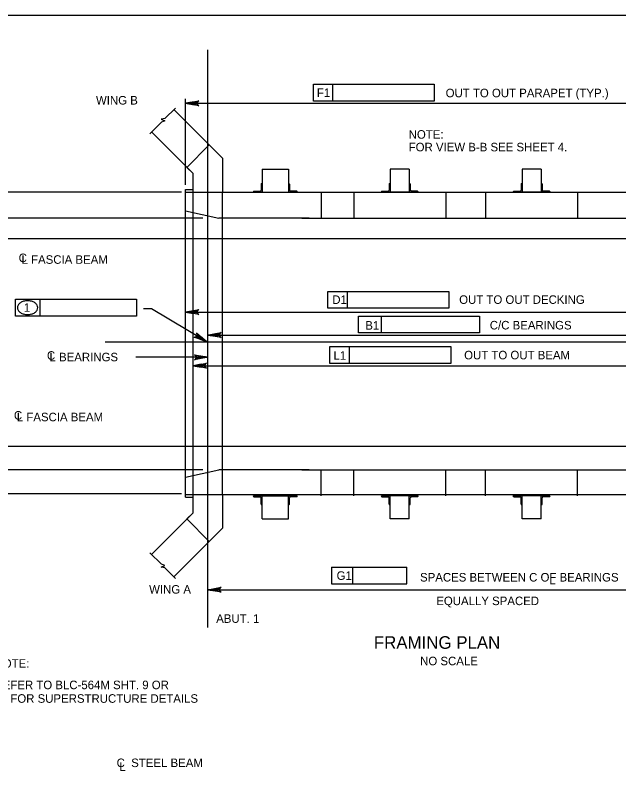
# Model space of a CAD drawing. Extents: x 638175 to 640495, y 294277 to 298435.
# Drawn here: x 638550.4 to 638762.6, y 294590.7 to 294856.5 of the extents above; entities that cross this region are included whole.
import ezdxf

# ---------------------------------------------------------------- set-up
doc = ezdxf.new("R2010")
doc.units = 0
for name, color, linetype in [('2', 7, 'Continuous'), ('3', 7, 'Continuous'), ('4', 7, 'Continuous')]:
    doc.layers.add(name, color=color, linetype=linetype)

msp = doc.modelspace()

# ---------------------------------------------------------------- linework, layer by layer
at = {"layer": '2'}
for p, q in [((638475.46, 294856.46), (639261.46, 294856.46)), ((638623.24, 294806.15), (638606.16, 294823.24)), ((638612.95, 294800.71), (638598.29, 294815.37)), ((638610.74, 294802.91), (638618.61, 294810.78)), ((638623.24, 294806.15), (638623.24, 294794.15)), ((638612.95, 294800.71), (638610.74, 294802.91)), ((638637.18, 294802.24), (638646.41, 294802.24)), ((638637.18, 294802.24), (638637.18, 294794.15)), ((638646.41, 294802.24), (638646.41, 294794.15)), ((638688.9, 294802.24), (638682.17, 294802.24)), ((638682.17, 294802.24), (638682.17, 294794.15)), ((638688.9, 294802.24), (638688.9, 294794.15)), ((638735.26, 294802.24), (638728.53, 294802.24)), ((638735.26, 294802.24), (638728.53, 294802.24)), ((638728.53, 294802.24), (638728.53, 294794.15)), ((638735.26, 294802.24), (638735.26, 294794.15)), ((638612.95, 294794.15), (638612.95, 294800.71)), ((638636.81, 294797.05), (638636.81, 294794.87)), ((638636.99, 294797.24), (638637.18, 294797.24)), ((638637.18, 294797.24), (638637.18, 294794.15)), ((638646.59, 294797.24), (638646.41, 294797.24)), ((638646.41, 294797.24), (638646.41, 294794.15)), ((638646.78, 294797.05), (638646.78, 294794.87)), ((638681.81, 294797.05), (638681.81, 294794.87)), ((638681.99, 294797.24), (638682.17, 294797.24)), ((638682.17, 294797.24), (638682.17, 294794.15)), ((638689.08, 294797.24), (638688.9, 294797.24)), ((638688.9, 294797.24), (638688.9, 294794.15)), ((638689.26, 294797.05), (638689.26, 294794.87)), ((638728.17, 294797.05), (638728.17, 294794.87)), ((638728.35, 294797.24), (638728.53, 294797.24)), ((638728.53, 294797.24), (638728.53, 294794.15)), ((638735.44, 294797.24), (638735.26, 294797.24)), ((638735.26, 294797.24), (638735.26, 294794.15)), ((638735.62, 294797.05), (638735.62, 294794.87)), ((638610.28, 294686.89), (638610.28, 294795.1)), ((638610.28, 294795.1), (638612.95, 294795.1)), ((638610.28, 294794.15), (638813.34, 294794.15)), ((638612.95, 294687.85), (638612.95, 294794.15)), ((638623.24, 294687.85), (638623.24, 294794.15)), ((638634.09, 294794.33), (638634.09, 294794.15)), ((638637.18, 294794.15), (638634.09, 294794.15)), ((638634.27, 294794.51), (638636.45, 294794.51)), ((638637.18, 294794.15), (638646.41, 294794.15)), ((638646.41, 294794.15), (638649.5, 294794.15)), ((638649.32, 294794.51), (638647.14, 294794.51)), ((638649.5, 294794.33), (638649.5, 294794.15)), ((638657.96, 294794.15), (638657.96, 294785.02)), ((638669.36, 294794.15), (638669.36, 294785.02)), ((638679.08, 294794.33), (638679.08, 294794.15)), ((638682.17, 294794.15), (638679.08, 294794.15)), ((638679.26, 294794.51), (638681.44, 294794.51)), ((638688.9, 294794.15), (638682.17, 294794.15)), ((638688.9, 294794.15), (638691.99, 294794.15)), ((638691.81, 294794.51), (638689.63, 294794.51)), ((638691.99, 294794.33), (638691.99, 294794.15)), ((638701.7, 294794.15), (638701.7, 294785.02)), ((638715.73, 294794.15), (638715.73, 294785.02)), ((638725.44, 294794.33), (638725.44, 294794.15)), ((638728.53, 294794.15), (638725.44, 294794.15)), ((638725.63, 294794.51), (638727.81, 294794.51)), ((638736.52, 294794.15), (638727.28, 294794.15)), ((638735.26, 294794.15), (638728.53, 294794.15)), ((638735.26, 294794.15), (638738.35, 294794.15)), ((638738.17, 294794.51), (638735.99, 294794.51)), ((638738.35, 294794.33), (638738.35, 294794.15)), ((638748.07, 294794.15), (638748.07, 294785.02)), ((638610.28, 294787.63), (638621.95, 294785.02)), ((638653.74, 294785.02), (638621.95, 294785.02)), ((638651.07, 294785.02), (638801.67, 294785.02)), ((638610.28, 294693.94), (638621.95, 294696.54)), ((638653.74, 294696.54), (638621.95, 294696.54)), ((638651.07, 294696.54), (638801.67, 294696.54)), ((638657.96, 294687.42), (638657.96, 294696.54)), ((638669.36, 294687.42), (638669.36, 294696.54)), ((638701.7, 294687.42), (638701.7, 294696.54)), ((638715.73, 294687.42), (638715.73, 294696.54)), ((638748.07, 294687.42), (638748.07, 294696.54)), ((638610.28, 294687.85), (638813.34, 294687.85)), ((638610.28, 294686.89), (638612.95, 294686.89)), ((638612.95, 294681.45), (638612.95, 294687.85)), ((638623.24, 294687.85), (638623.24, 294676.01)), ((638634.09, 294687.24), (638634.09, 294687.42)), ((638637.18, 294687.42), (638634.09, 294687.42)), ((638634.27, 294687.06), (638636.45, 294687.06)), ((638637.18, 294687.42), (638646.41, 294687.42)), ((638637.18, 294684.33), (638637.18, 294687.42)), ((638637.18, 294679.33), (638637.18, 294687.42)), ((638646.41, 294687.42), (638649.5, 294687.42)), ((638646.41, 294684.33), (638646.41, 294687.42)), ((638646.41, 294679.33), (638646.41, 294687.42)), ((638649.32, 294687.06), (638647.14, 294687.06)), ((638649.5, 294687.24), (638649.5, 294687.42)), ((638679.08, 294687.24), (638679.08, 294687.42)), ((638682.17, 294687.42), (638679.08, 294687.42)), ((638679.26, 294687.06), (638681.44, 294687.06)), ((638688.9, 294687.42), (638682.17, 294687.42)), ((638682.17, 294684.33), (638682.17, 294687.42)), ((638682.17, 294679.33), (638682.17, 294687.42)), ((638688.9, 294684.33), (638688.9, 294687.42)), ((638688.9, 294687.42), (638691.99, 294687.42)), ((638688.9, 294679.33), (638688.9, 294687.42)), ((638691.81, 294687.06), (638689.63, 294687.06)), ((638691.99, 294687.24), (638691.99, 294687.42)), ((638725.44, 294687.24), (638725.44, 294687.42)), ((638728.53, 294687.42), (638725.44, 294687.42)), ((638725.63, 294687.06), (638727.81, 294687.06)), ((638736.52, 294687.42), (638727.28, 294687.42)), ((638735.26, 294687.42), (638728.53, 294687.42)), ((638728.53, 294684.33), (638728.53, 294687.42)), ((638728.53, 294679.33), (638728.53, 294687.42)), ((638735.26, 294684.33), (638735.26, 294687.42)), ((638735.26, 294687.42), (638738.35, 294687.42)), ((638735.26, 294679.33), (638735.26, 294687.42)), ((638738.17, 294687.06), (638735.99, 294687.06)), ((638738.35, 294687.24), (638738.35, 294687.42)), ((638636.81, 294684.51), (638636.81, 294686.69)), ((638636.99, 294684.33), (638637.18, 294684.33)), ((638646.59, 294684.33), (638646.41, 294684.33)), ((638646.78, 294684.51), (638646.78, 294686.69)), ((638681.81, 294684.51), (638681.81, 294686.69)), ((638681.99, 294684.33), (638682.17, 294684.33)), ((638689.08, 294684.33), (638688.9, 294684.33)), ((638689.26, 294684.51), (638689.26, 294686.69)), ((638728.17, 294684.51), (638728.17, 294686.69)), ((638728.35, 294684.33), (638728.53, 294684.33)), ((638735.44, 294684.33), (638735.26, 294684.33)), ((638735.62, 294684.51), (638735.62, 294686.69)), ((638612.95, 294681.45), (638598.29, 294666.8)), ((638612.95, 294681.45), (638610.74, 294679.25)), ((638610.74, 294679.25), (638618.61, 294671.38)), ((638637.18, 294679.33), (638646.41, 294679.33)), ((638688.9, 294679.33), (638682.17, 294679.33)), ((638735.26, 294679.33), (638728.53, 294679.33)), ((638735.26, 294679.33), (638728.53, 294679.33)), ((638623.24, 294676.01), (638606.16, 294658.92))]:
    msp.add_line(p, q, dxfattribs=at)
for centre, radius, start, end in [((638636.99, 294797.05), 0.182, 90, 179.9984), ((638646.59, 294797.05), 0.182, 0.0016, 90), ((638681.99, 294797.05), 0.182, 90, 179.9984), ((638689.08, 294797.05), 0.182, 0.0016, 90), ((638728.35, 294797.05), 0.182, 90, 179.9984), ((638735.44, 294797.05), 0.182, 0.0016, 90), ((638634.27, 294794.33), 0.182, 90, 179.9984), ((638636.45, 294794.87), 0.364, 270, 359.9984), ((638647.14, 294794.87), 0.364, 180.0016, 270), ((638649.32, 294794.33), 0.182, 0.0016, 90), ((638679.26, 294794.33), 0.182, 90, 179.9984), ((638681.44, 294794.87), 0.364, 270, 359.9984), ((638689.63, 294794.87), 0.364, 180.0016, 270), ((638691.81, 294794.33), 0.182, 0.0016, 90), ((638725.63, 294794.33), 0.182, 90, 179.9984), ((638727.81, 294794.87), 0.364, 270, 359.9984), ((638735.99, 294794.87), 0.364, 180.0016, 270), ((638738.17, 294794.33), 0.182, 0.0016, 90), ((638634.27, 294687.24), 0.182, 180.0016, 270), ((638636.45, 294686.69), 0.364, 0.0016, 90), ((638647.14, 294686.69), 0.364, 90, 179.9984), ((638649.32, 294687.24), 0.182, 270, 359.9984), ((638679.26, 294687.24), 0.182, 180.0016, 270), ((638681.44, 294686.69), 0.364, 0.0016, 90), ((638689.63, 294686.69), 0.364, 90, 179.9984), ((638691.81, 294687.24), 0.182, 270, 359.9984), ((638725.63, 294687.24), 0.182, 180.0016, 270), ((638727.81, 294686.69), 0.364, 0.0016, 90), ((638735.99, 294686.69), 0.364, 90, 179.9984), ((638738.17, 294687.24), 0.182, 270, 359.9984), ((638636.99, 294684.51), 0.182, 180.0016, 270), ((638646.59, 294684.51), 0.182, 270, 359.9984), ((638681.99, 294684.51), 0.182, 180.0016, 270), ((638689.08, 294684.51), 0.182, 270, 359.9984), ((638728.35, 294684.51), 0.182, 180.0016, 270), ((638735.44, 294684.51), 0.182, 270, 359.9984)]:
    msp.add_arc(centre, radius, start, end, dxfattribs=at)
at = {"layer": '3'}
for p, q in [((638618.1, 294641.12), (638618.1, 294844.19)), ((638602.98, 294820.06), (638606.72, 294823.79)), ((638602.98, 294820.06), (638601.69, 294819.9)), ((638601.69, 294819.9), (638603.02, 294819.24)), ((638597.68, 294814.76), (638601.77, 294818.84)), ((638603.02, 294819.24), (638601.77, 294818.84)), ((638597.68, 294667.4), (638601.77, 294663.32)), ((638601.69, 294662.26), (638603.02, 294662.92)), ((638603.02, 294662.92), (638601.77, 294663.32)), ((638602.98, 294662.1), (638601.69, 294662.26)), ((638602.98, 294662.1), (638606.72, 294658.37))]:
    msp.add_line(p, q, dxfattribs=at)
at = {"layer": '4'}
for p, q in [((638655.18, 294832.13), (638697.69, 294832.13)), ((638655.18, 294826.23), (638655.18, 294832.13)), ((638662.07, 294826.23), (638662.07, 294832.13)), ((638697.69, 294832.13), (638697.69, 294826.23)), ((638610.28, 294796.82), (638610.28, 294826.96)), ((638610.28, 294825.45), (638813.34, 294825.45)), ((638697.69, 294826.23), (638655.18, 294826.23)), ((638608.84, 294794.15), (638490.2, 294794.15)), ((638616.29, 294785.02), (638503.92, 294785.02)), ((638821.74, 294777.76), (638521.33, 294777.76)), ((638660.27, 294753.34), (638660.27, 294759.25)), ((638660.27, 294759.25), (638702.79, 294759.25)), ((638667.16, 294753.34), (638667.16, 294759.25)), ((638702.79, 294759.25), (638702.79, 294753.34)), ((638550.51, 294750.63), (638550.51, 294756.54)), ((638550.51, 294756.54), (638593.03, 294756.54)), ((638559.15, 294750.63), (638559.15, 294756.54)), ((638593.03, 294756.54), (638593.03, 294750.63)), ((638702.79, 294753.34), (638660.27, 294753.34)), ((638593.03, 294750.63), (638550.51, 294750.63)), ((638598.32, 294753.19), (638595.49, 294753.19)), ((638617.7, 294741.57), (638598.32, 294753.19)), ((638610.28, 294752.01), (638813.34, 294752.01)), ((638671.03, 294750.64), (638713.55, 294750.64)), ((638671.03, 294744.73), (638671.03, 294750.64)), ((638679.1, 294744.73), (638679.1, 294750.64)), ((638713.55, 294750.64), (638713.55, 294744.73)), ((638618.1, 294743.95), (638805.68, 294743.95)), ((638713.55, 294744.73), (638671.03, 294744.73)), ((638582.06, 294741.57), (638855.54, 294741.57)), ((638660.95, 294739.86), (638703.47, 294739.86)), ((638660.95, 294733.95), (638660.95, 294739.86)), ((638667.84, 294733.95), (638667.84, 294739.86)), ((638703.47, 294739.86), (638703.47, 294733.95)), ((638618.1, 294736.11), (638592.77, 294736.11)), ((638612.95, 294733.17), (638810.82, 294733.17)), ((638703.47, 294733.95), (638660.95, 294733.95)), ((638821.74, 294704.77), (638521.03, 294704.77)), ((638616.29, 294696.54), (638503.92, 294696.54)), ((638608.84, 294688.11), (638490.2, 294688.11)), ((638661.54, 294662.3), (638661.53, 294656.39)), ((638661.54, 294662.3), (638688.05, 294662.3)), ((638669.09, 294656.39), (638669.1, 294662.3)), ((638688.04, 294656.39), (638688.05, 294662.3)), ((638618.1, 294653.91), (638618.1, 294658.88)), ((638661.53, 294656.39), (638688.04, 294656.39)), ((638618.1, 294654.38), (638805.68, 294654.38))]:
    msp.add_line(p, q, dxfattribs=at)
for points in [[(638610.28, 294825.45), (638614.94, 294826.32), (638614.58, 294826.07), (638614.39, 294825.76), (638614.34, 294825.45), (638614.39, 294825.13), (638614.58, 294824.82), (638614.94, 294824.57), (638610.28, 294825.45), (638614.58, 294824.82), (638614.39, 294825.13), (638610.28, 294825.45), (638614.34, 294825.45), (638614.39, 294825.76), (638610.28, 294825.45), (638614.58, 294826.07)], [(638610.28, 294752.01), (638614.94, 294752.88), (638614.58, 294752.63), (638614.39, 294752.32), (638614.34, 294752.01), (638614.39, 294751.7), (638614.58, 294751.38), (638614.94, 294751.13), (638610.28, 294752.01), (638614.58, 294751.38), (638614.39, 294751.7), (638610.28, 294752.01), (638614.34, 294752.01), (638614.39, 294752.32), (638610.28, 294752.01), (638614.58, 294752.63)], [(638617.7, 294741.57), (638613.25, 294743.22), (638613.69, 294743.25), (638614.01, 294743.42), (638614.22, 294743.66), (638614.33, 294743.96), (638614.33, 294744.32), (638614.15, 294744.72), (638617.7, 294741.57), (638614.33, 294744.32), (638614.33, 294743.96), (638617.7, 294741.57), (638614.22, 294743.66), (638614.01, 294743.42), (638617.7, 294741.57), (638613.69, 294743.25)], [(638618.1, 294743.95), (638622.76, 294744.83), (638622.4, 294744.58), (638622.21, 294744.27), (638622.16, 294743.95), (638622.21, 294743.64), (638622.4, 294743.33), (638622.76, 294743.08), (638618.1, 294743.95), (638622.4, 294743.33), (638622.21, 294743.64), (638618.1, 294743.95), (638622.16, 294743.95), (638622.21, 294744.27), (638618.1, 294743.95), (638622.4, 294744.58)], [(638618.1, 294736.11), (638613.44, 294735.24), (638613.79, 294735.49), (638613.98, 294735.8), (638614.03, 294736.11), (638613.98, 294736.43), (638613.79, 294736.74), (638613.44, 294736.99), (638618.1, 294736.11), (638613.79, 294736.74), (638613.98, 294736.43), (638618.1, 294736.11), (638614.03, 294736.11), (638613.98, 294735.8), (638618.1, 294736.11), (638613.79, 294735.49)], [(638612.95, 294733.17), (638617.61, 294734.05), (638617.25, 294733.8), (638617.07, 294733.48), (638617.01, 294733.17), (638617.07, 294732.86), (638617.25, 294732.55), (638617.61, 294732.3), (638612.95, 294733.17), (638617.25, 294732.55), (638617.07, 294732.86), (638612.95, 294733.17), (638617.01, 294733.17), (638617.07, 294733.48), (638612.95, 294733.17), (638617.25, 294733.8)], [(638618.1, 294654.38), (638622.76, 294655.25), (638622.4, 294655), (638622.21, 294654.69), (638622.16, 294654.38), (638622.21, 294654.06), (638622.4, 294653.75), (638622.76, 294653.5), (638618.1, 294654.38), (638622.4, 294653.75), (638622.21, 294654.06), (638618.1, 294654.38), (638622.16, 294654.38), (638622.21, 294654.69), (638618.1, 294654.38), (638622.4, 294655)]]:
    msp.add_lwpolyline(points, dxfattribs=at)
for points in [[(638613.23, 294824.95), (638613.23, 294825.94), (638610.28, 294825.45)], [(638613.11, 294751.53), (638613.11, 294752.48), (638610.28, 294752.01)], [(638615.51, 294743.43), (638615.03, 294742.62), (638617.7, 294741.57)], [(638621.41, 294743.46), (638621.41, 294744.45), (638618.46, 294743.95)], [(638614.87, 294736.59), (638614.87, 294735.64), (638617.7, 294736.11)], [(638615.78, 294732.7), (638615.78, 294733.65), (638612.95, 294733.17)], [(638621.1, 294654.88), (638621.1, 294653.88), (638618.1, 294654.38)]]:
    msp.add_lwpolyline(points, close=True, dxfattribs=at)
for centre, radius, start, end in [((638554.74, 294750.73), 5.27, 90, 105.6708), ((638554.74, 294750.73), 5.27, 74.3292, 90), ((638552.83, 294753.58), 1.68, 148.5507, 180), ((638552.83, 294753.58), 1.68, 180, 211.4493), ((638553.75, 294753.02), 2.75, 124.109, 148.5507), ((638554.35, 294752.13), 3.82, 105.6708, 124.109), ((638555.13, 294752.13), 3.82, 55.891, 74.3292), ((638555.73, 294753.02), 2.75, 31.4493, 55.891), ((638556.65, 294753.58), 1.68, 0, 31.4493), ((638556.65, 294753.58), 1.68, 328.5507, 0), ((638553.75, 294754.13), 2.75, 211.4493, 235.891), ((638554.35, 294755.02), 3.82, 235.891, 254.3292), ((638554.74, 294756.42), 5.27, 254.3292, 270), ((638554.74, 294756.42), 5.27, 270, 285.6708), ((638555.13, 294755.02), 3.82, 285.6708, 304.109), ((638555.73, 294754.13), 2.75, 304.109, 328.5507)]:
    msp.add_arc(centre, radius, start, end, dxfattribs=at)

# ---------------------------------------------------------------- texts
for s, height, p in [('F1', 3, (638656.42, 294827.66)), ('OUT TO OUT PARAPET (TYP.)', 3, (638701.68, 294827.57)), ('WING B', 3, (638578.78, 294825.01)), ('NOTE:', 3, (638688.68, 294812.99)), ('FOR VIEW B-B SEE SHEET 4.', 3, (638688.68, 294808.55)), ('C', 3, (638551.6, 294769.59)), ('L FASCIA BEAM', 3, (638552.62, 294769)), ('D1', 3, (638661.83, 294754.88)), ('OUT TO OUT DECKING', 3, (638706.43, 294754.91)), ('1', 3, (638553.44, 294752.12)), ('B1', 3, (638673.44, 294745.84)), ('C/C BEARINGS', 3, (638717.19, 294745.91)), ('C', 3, (638561.55, 294735.25)), ('L BEARINGS', 3, (638562.45, 294734.71)), ('L1', 3, (638662.26, 294735.25)), ('OUT TO OUT BEAM', 3, (638708.18, 294735.39)), ('C', 3, (638549.94, 294714.2)), ('L FASCIA BEAM', 3, (638550.96, 294713.62)), ('SPACES BETWEEN C OF BEARINGS', 3, (638692.68, 294657.26)), ('L', 3, (638738.11, 294656.28)), ('WING A', 3, (638597.46, 294653)), ('EQUALLY SPACED', 3, (638698.38, 294648.96)), ('ABUT. 1', 3, (638621.03, 294642.73)), ('FRAMING PLAN', 4.4292, (638676.44, 294633.6)), ('NOTE:', 3, (638543.1, 294626.94)), ('NO SCALE', 3, (638692.71, 294627.81)), ('REFER TO BLC-564M SHT. 9 OR', 3, (638543.1, 294619.4)), ('10 FOR SUPERSTRUCTURE DETAILS', 3, (638543.1, 294614.62)), ('C  STEEL BEAM', 3, (638586.03, 294592)), ('L', 3, (638586.97, 294590.67))]:
    msp.add_text(s, height=height, dxfattribs=at).set_placement(p)
msp.add_text('G1', height=3, rotation=359.9382, dxfattribs=at).set_placement((638663.35, 294657.85))

doc.saveas('drawing.dxf')
